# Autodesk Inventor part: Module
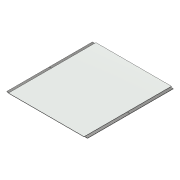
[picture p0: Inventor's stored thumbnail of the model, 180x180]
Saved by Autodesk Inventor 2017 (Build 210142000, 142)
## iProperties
Part Number: Module
Material: 一般
Document SubType Name: Modeling
Designer: kyushu-hep
Density: 1 g/cm^3
Appearance: 既定
Author: kyushu-hep
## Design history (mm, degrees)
sketch "スケッチ1"
  geometry: L1 (-17.274, 15.65)-(20.836, 15.65); L2 (20.836, 15.65)-(20.836, -24.8); L3 (20.836, -24.8)-(-17.274, -24.8); L4 (-17.274, -24.8)-(-17.274, 15.65); 1 further point
  constraints: 8 end point, 2 parallel, 1 horizontal, 1 perpendicular
  dimensions: "d0" = 38.11 distance of L1.start L1.end; "d1" = 40.45 distance of L3.end L1.start
extrude "押し出し1" new body sketch "スケッチ1" distance "d2" = 0.175; taper "d3" = 0 deg
sketch "スケッチ2"
  geometry: L1 (-16.024, 16.019)-(19.586, 16.019); L2 (19.586, 16.019)-(19.586, -25.169); L3 (19.586, -25.169)-(-16.024, -25.169); L4 (-16.024, -25.169)-(-16.024, 16.019); L5 (-17.274, -24.8)-(20.836, -24.8) reference; L6 (-17.274, -24.8)-(-17.274, 15.65) reference; 1 further point
  constraints: 8 end point, 2 parallel, 1 horizontal, 1 perpendicular
  dimensions: "d4" = 35.61 distance of L1.start L1.end; "d5" = 41.188 distance of L3.end L1.start; "d6" = 0.369 distance between parallel lines of L3 L5; "d7" = 1.25 distance between parallel lines of L6 L4
extrude "押し出し2" join sketch "スケッチ2" distance "d8" = 0.15; taper "d9" = 0 deg
sketch "スケッチ5"
  geometry: L1 (-17.274, -4.775)-(-16.274, -4.775); L2 (-16.274, -4.775)-(-16.274, -4.825); L3 (-16.274, -4.825)-(-17.274, -4.825); L4 (-17.274, -4.825)-(-17.274, -4.775); L5 (20.836, -24.8)-(20.836, 15.65) reference; L6 (20.836, 15.65)-(19.586, 15.65) reference; L7 (19.836, -4.825)-(20.836, -4.825); L8 (20.836, -4.825)-(20.836, -4.875); L9 (20.836, -4.875)-(19.836, -4.875); L10 (19.836, -4.875)-(19.836, -4.825); L11 (-17.274, 15.65)-(-17.274, -24.8) reference; 1 further point
  constraints: 16 end point, 4 parallel, 2 horizontal, 2 perpendicular, 1 collinear, 1 point on line
  dimensions: "d19" = 1 distance of L2.end L3.end; "d20" = 0.05 distance of L3.end L1.start; "d21" = 20.425 distance between parallel lines of L6 L1; "d22" = 0.05 distance of L9.end L7.start; "d23" = 0 distance between parallel lines of L7 L3
extrude "押し出し4" join sketch "スケッチ5" distance "d24" = 0.05; taper "d25" = 0 deg
node "ソリッド1"
